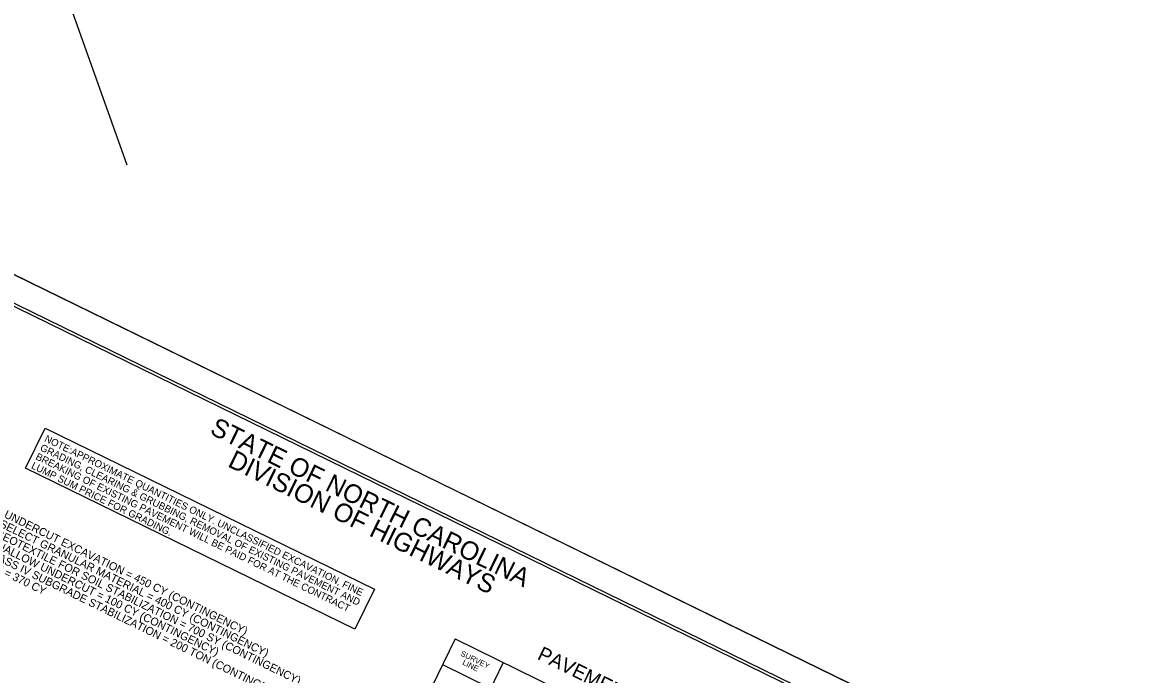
# Model space of a CAD drawing. Extents: x 1523741 to 1527628, y 632733 to 635404.
# Drawn here: x 1526640 to 1527628, y 633859 to 634429 of the extents above; entities that cross this region are included whole.
import ezdxf

# ---------------------------------------------------------------- set-up
doc = ezdxf.new("R2010")
doc.units = 0
for name, color, linetype in [('Scratch_Level_0', 7, 'Continuous'), ('Sheet Cutting Line CELL', 7, 'Continuous'), ('Sheet Plot Border Inside CELL', 7, 'Continuous'), ('Sheet Plot Border Outside CELL', 7, 'Continuous'), ('Sheet Summary Combination CELL', 7, 'Continuous'), ('Sheet Summary Combination Grid CELL', 7, 'Continuous'), ('Sheet Summary Earthwork CELL', 7, 'Continuous')]:
    doc.layers.add(name, color=color, linetype=linetype)

msp = doc.modelspace()

# ---------------------------------------------------------------- linework, layer by layer
at = {"layer": 'Scratch_Level_0'}
msp.add_line((1526483.1, 635003.21), (1526731.38, 634304.38), dxfattribs=at)
at = {"layer": 'Sheet Cutting Line CELL'}
msp.add_line((1527628.42, 633721.36), (1526115.65, 634461.22), dxfattribs=at)
at = {"layer": 'Sheet Plot Border Inside CELL'}
msp.add_lwpolyline([(1527614.51, 633703.17), (1526117.47, 634435.34), (1525653.91, 633487.53), (1527150.96, 632755.35)], close=True, dxfattribs=at)
at = {"layer": 'Sheet Plot Border Outside CELL'}
msp.add_lwpolyline([(1527628.42, 633721.36), (1526115.65, 634461.22), (1525632.37, 633473.07), (1527145.14, 632733.21)], close=True, dxfattribs=at)
at = {"layer": 'Sheet Summary Combination CELL'}
msp.add_lwpolyline([(1527602.16, 633706.37), (1526254.69, 634365.39), (1525793.37, 633422.16), (1527140.85, 632763.14)], close=True, dxfattribs=at)
at = {"layer": 'Sheet Summary Combination Grid CELL'}
for p, q in [((1527018.54, 633889.77), (1526842.8, 633530.44)), ((1527018.54, 633889.77), (1527397.68, 633704.34)), ((1527060.67, 633869.16), (1526901.41, 633543.52)), ((1527007.56, 633867.31), (1527386.69, 633681.88))]:
    msp.add_line(p, q, dxfattribs=at)
at = {"layer": 'Sheet Summary Earthwork CELL'}
msp.add_lwpolyline([(1526659.94, 634074.2), (1526948, 633933.32), (1526930.82, 633898.2), (1526642.76, 634039.08)], close=True, dxfattribs=at)

# ---------------------------------------------------------------- texts
at = {"layer": 'Sheet Summary Combination CELL'}
for s, height, rotation, p in [('STATE OF NORTH CAROLINA', 16.2501, 333.93772, (1526803.2, 634069.46)), ('DIVISION OF HIGHWAYS', 16.2501, 333.93772, (1526818.85, 634040.93)), ('UNDERCUT EXCAVATION = 450 CY (CONTINGENCY)', 7, 333.93772, (1526623.58, 633996.34)), ('SELECT GRANULAR MATERIAL = 400 CY (CONTINGENCY)', 7, 333.93772, (1526619.55, 633988.09)), ('SHALLOW UNDERCUT = 100 CY (CONTINGENCY)', 7, 333.93772, (1526611.48, 633971.61)), ('GEOTEXTILE FOR SOIL STABILIZATION = 700 SY (CONTINGENCY)', 7, 333.93772, (1526615.51, 633979.85)), ('CLASS IV SUBGRADE STABILIZATION = 200 TON (CONTINGENCY)', 7, 333.93772, (1526607.45, 633963.36)), ('DDE = 370 CY', 7, 333.93772, (1526603.42, 633955.12)), ('SURVEY', 4.8, 333.93772, (1527022.83, 633875.44)), ('PAVEMENT REMOVAL SUMMARY', 12.5001, 333.94965, (1527089.67, 633872.55)), ('LINE', 4.8, 333.93772, (1527024.47, 633867.63))]:
    msp.add_text(s, height=height, rotation=rotation, dxfattribs=at).set_placement(p)
at = {"layer": 'Sheet Summary Earthwork CELL'}
for s, p in [('NOTE:APPROXIMATE QUANTITIES ONLY. UNCLASSIFIED EXCAVATION, FINE', (1526658.84, 634062.8)), ('GRADING, CLEARING & GRUBBING, REMOVAL OF EXISTING PAVEMENT AND', (1526654.99, 634054.94)), ('BREAKING OF EXISTING PAVEMENT WILL BE PAID FOR AT THE CONTRACT', (1526651.15, 634047.08)), ('LUMP SUM PRICE FOR GRADING.', (1526647.3, 634039.22))]:
    msp.add_text(s, height=6.25, rotation=333.93772, dxfattribs=at).set_placement(p)

doc.saveas('drawing.dxf')
